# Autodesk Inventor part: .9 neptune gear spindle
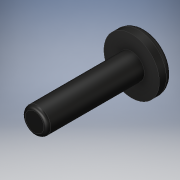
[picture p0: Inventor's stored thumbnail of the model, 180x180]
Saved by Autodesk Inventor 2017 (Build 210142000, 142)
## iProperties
Created: 2017-04
Part Number: .9 neptune gear spindle
Material: Generic
Document SubType Name: Modeling
Designer: Stan
Density: 1 g/cm^3
Appearance: Glossy - Black
Author: Stan
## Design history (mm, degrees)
sketch "Sketch1"
  geometry: C1 r 6.35 at (0, 0); 1 further point
  constraints: 1 centre point, 1 coincident
  dimensions: "d0" = 12.7 diameter of C1
extrude "Extrusion1" new body sketch "Sketch1" distance "d1" = 3.175; taper "d2" = 0 deg
sketch "Sketch2"
  geometry: C1 r 2.921 at (0, 0); 1 further point
  constraints: 1 centre point, 1 coincident
  dimensions: "d3" = 5.842 diameter of C1
extrude "Extrusion2" join sketch "Sketch2" distance "d4" = 22.225; taper "d5" = 0 deg
fillet "Fillet1" dims "d6" = 1.5875
fillet "Fillet2" dims "d7" = 0.79375
body "Solid1"
